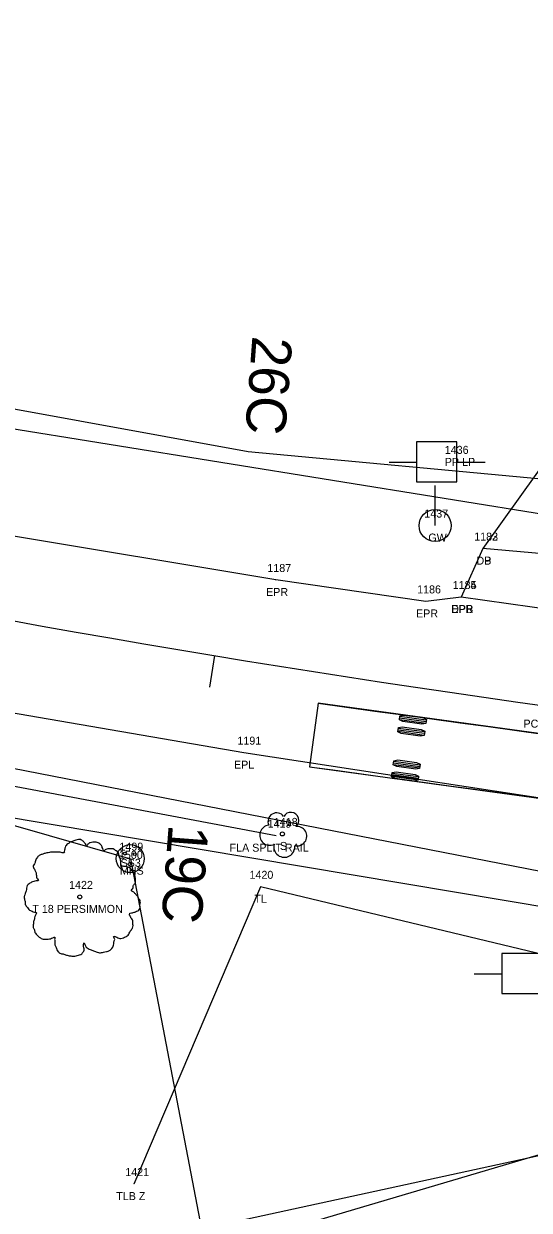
# Model space of a CAD drawing. Extents: x 1812113 to 1819860, y 1177290 to 1181185.
# Drawn here: x 1813468 to 1813531.1, y 1178709.1 to 1178857.4 of the extents above; entities that cross this region are included whole.
import ezdxf

# ---------------------------------------------------------------- set-up
doc = ezdxf.new("R2010")
doc.units = 0
for name, color, linetype in [('RD_EX_DR_Inlet', 7, 'Continuous'), ('RD_EX_Driveway', 7, 'Continuous'), ('RD_EX_Driveway_txCode', 7, 'Continuous'), ('RD_EX_Fence_Other', 7, 'Continuous'), ('RD_EX_Fence_Other_txCode', 7, 'Continuous'), ('RD_EX_H2O', 7, 'Continuous'), ('RD_EX_Road', 7, 'Continuous'), ('RD_EX_Road_txCode', 7, 'Continuous'), ('RD_EX_RW', 7, 'Continuous'), ('RD_EX_UT', 7, 'Continuous'), ('RD_EX_UT_txCode', 7, 'Continuous'), ('RD_EX_VEG', 7, 'Continuous'), ('RD_EX_VEG_txCode', 7, 'Continuous'), ('RD_HC_CL', 7, 'Continuous'), ('RD_HC_Data_Tic', 7, 'Continuous'), ('RD_HC_txCode', 7, 'Continuous'), ('RD_PD_CstnLmt', 7, 'Continuous'), ('RD_Sketch5', 7, 'Continuous'), ('RD_SMD_Locator', 7, 'Continuous')]:
    doc.layers.add(name, color=color, linetype=linetype)

msp = doc.modelspace()

# ---------------------------------------------------------------- linework, layer by layer
at = {"layer": 'RD_EX_DR_Inlet'}
for centre, radius in [((1813481.28, 1178753.05), 1.75), ((1813480.62, 1178753.68), 0.175), ((1813481.84, 1178753.61), 0.175), ((1813481.19, 1178752.38), 0.175)]:
    msp.add_circle(centre, radius, dxfattribs=at)
at = {"layer": 'RD_EX_Driveway'}
for points in [[(1813615.6, 1178795.77), (1813617.78, 1178806.55), (1813543.17, 1178816.74), (1813525.31, 1178791.79)], [(1813638.42, 1178791.25), (1813630.13, 1178786.38), (1813613.34, 1178784.52), (1813588.43, 1178786.24), (1813525.31, 1178791.79), (1813522.62, 1178785.74)]]:
    msp.add_lwpolyline(points, dxfattribs=at)
at = {"layer": 'RD_EX_Fence_Other'}
msp.add_lwpolyline([(1813499.51, 1178755.92), (1813424.16, 1178770.12), (1813422.76, 1178764.09)], dxfattribs=at)
at = {"layer": 'RD_EX_H2O'}
msp.add_lwpolyline([(1813499.62, 1178706.37), (1813533.11, 1178716.31), (1813566.87, 1178706.45), (1813581.02, 1178703.79), (1813602.73, 1178697.66), (1813630.18, 1178688.94), (1813658.74, 1178690.22), (1813683.52, 1178690.56), (1813733.77, 1178695.63), (1813767.86, 1178725.16), (1813778.94, 1178729.95)], dxfattribs=at)
at = {"layer": 'RD_EX_Road'}
for p, q in [((1813499.47, 1178787.87), (1813450.56, 1178796.06)), ((1813518.21, 1178785.19), (1813499.47, 1178787.87)), ((1813522.62, 1178785.74), (1813518.21, 1178785.19)), ((1813596.09, 1178775.31), (1813522.62, 1178785.74))]:
    msp.add_line(p, q, dxfattribs=at)
msp.add_lwpolyline([(1813732.94, 1178707.95), (1813689.88, 1178731.75), (1813641.71, 1178744.36), (1813593.37, 1178752.09), (1813544.49, 1178758.77), (1813495.45, 1178766.29), (1813446.8, 1178774.66), (1813426.54, 1178777.95), (1813403.21, 1178782.55), (1813398.65, 1178783.84), (1813350.68, 1178796.09), (1813343.23, 1178797.92), (1813318.7, 1178804.23), (1813303.26, 1178808.85), (1813256.8, 1178823.17), (1813209.81, 1178838.91), (1813163.27, 1178855.57)], dxfattribs=at)
at = {"layer": 'RD_EX_RW'}
for p, q in [((1813632.03, 1178780.07), (1813400.47, 1178817.38)), ((1813539.17, 1178745.92), (1813409.98, 1178767.65))]:
    msp.add_line(p, q, dxfattribs=at)
at = {"layer": 'RD_EX_UT'}
for p, q in [((1813522.06, 1178805.14), (1813517.06, 1178805.14)), ((1813517.06, 1178805.14), (1813517.06, 1178800.14)), ((1813522.06, 1178800.14), (1813522.06, 1178805.14)), ((1813513.63, 1178802.58), (1813517.1, 1178802.58)), ((1813521.99, 1178802.58), (1813525.63, 1178802.58)), ((1813517.06, 1178800.14), (1813522.06, 1178800.14)), ((1813519.36, 1178794.67), (1813519.36, 1178799.67)), ((1813532.69, 1178741.21), (1813527.69, 1178741.21)), ((1813527.69, 1178741.21), (1813527.69, 1178736.21)), ((1813524.26, 1178738.65), (1813527.73, 1178738.65)), ((1813527.69, 1178736.21), (1813532.69, 1178736.21))]:
    msp.add_line(p, q, dxfattribs=at)
for points in [[(1812996.89, 1178919.95), (1813204.49, 1178832.44), (1813481.3, 1178753.03), (1813490.2, 1178706.76)], [(1813817.45, 1178777.9), (1813490.2, 1178706.76), (1813294.33, 1178669.42)]]:
    msp.add_lwpolyline(points, dxfattribs=at)
msp.add_circle((1813519.36, 1178794.67), 2, dxfattribs=at)
at = {"layer": 'RD_EX_VEG'}
msp.add_lwpolyline([(1813615.69, 1178721.17), (1813497.56, 1178749.53), (1813481.72, 1178712.39)], dxfattribs=at)
for centre, radius in [((1813500.28, 1178756.14), 0.25), ((1813474.98, 1178748.27), 0.25), ((1813474.97, 1178748.25), 0.0001)]:
    msp.add_circle(centre, radius, dxfattribs=at)
for centre, radius, start, end in [((1813499.56, 1178757.69), 1.08, 34.9763, 204.756), ((1813501.33, 1178757.84), 0.995, 308.7626, 152.0467), ((1813498.72, 1178755.98), 1.26, 96.4518, 294.734), ((1813502.12, 1178755.86), 1.22, 256.5667, 98.1046), ((1813500.53, 1178754.54), 1.32, 166.8827, 5.7589)]:
    msp.add_arc(centre, radius, start, end, dxfattribs=at)
for points in [[(1813475.11, 1178755.44), (1813474.81, 1178755.46), (1813474.49, 1178755.36), (1813474.24, 1178755.26), (1813474.02, 1178755.19), (1813473.79, 1178755.09), (1813473.49, 1178754.91), (1813473.27, 1178754.71), (1813473.14, 1178754.46), (1813473.09, 1178754.24), (1813473.04, 1178753.96), (1813473.04, 1178753.79), (1813472.92, 1178753.76), (1813472.77, 1178753.79), (1813472.52, 1178753.86), (1813472.27, 1178753.86), (1813472.02, 1178753.86), (1813471.67, 1178753.84), (1813471.32, 1178753.84), (1813471.04, 1178753.79), (1813470.72, 1178753.74), (1813470.34, 1178753.61), (1813469.99, 1178753.49), (1813469.69, 1178753.24), (1813469.44, 1178752.76), (1813469.32, 1178752.41), (1813469.17, 1178752.16), (1813469.32, 1178751.72), (1813469.49, 1178751.37), (1813469.52, 1178751.17), (1813469.59, 1178750.74), (1813469.69, 1178750.52), (1813469.82, 1178750.32), (1813469.74, 1178750.29), (1813469.37, 1178750.24), (1813469.07, 1178750.14), (1813468.64, 1178749.92), (1813468.42, 1178749.69), (1813468.32, 1178749.37), (1813468.29, 1178749.02), (1813468.19, 1178748.82), (1813468.12, 1178748.54), (1813468.09, 1178748.47), (1813468.04, 1178748.14), (1813468.14, 1178747.69), (1813468.17, 1178747.34), (1813468.29, 1178747.12), (1813468.44, 1178746.94), (1813468.62, 1178746.69), (1813469.02, 1178746.47), (1813469.34, 1178746.37), (1813469.54, 1178746.34), (1813469.37, 1178745.84), (1813469.32, 1178745.49), (1813469.19, 1178745.09), (1813469.19, 1178745.02), (1813469.14, 1178744.54), (1813469.29, 1178744.22), (1813469.37, 1178743.84), (1813469.54, 1178743.62), (1813469.82, 1178743.32), (1813470.14, 1178743.09), (1813470.64, 1178742.97), (1813471.04, 1178742.99), (1813471.62, 1178743.17), (1813471.87, 1178743.24), (1813471.84, 1178743.07), (1813471.87, 1178742.69), (1813471.87, 1178742.27), (1813472.02, 1178741.94), (1813472.12, 1178741.67), (1813472.27, 1178741.42), (1813472.59, 1178741.19), (1813472.99, 1178741.12), (1813473.42, 1178740.97), (1813473.87, 1178740.89), (1813474.36, 1178740.87), (1813474.96, 1178741.02), (1813475.24, 1178741.14), (1813475.34, 1178741.32), (1813475.54, 1178741.69), (1813475.49, 1178741.92), (1813475.51, 1178742.52), (1813475.61, 1178742.34), (1813475.79, 1178741.99), (1813476.29, 1178741.69), (1813476.69, 1178741.52), (1813477.16, 1178741.37), (1813477.46, 1178741.29), (1813477.94, 1178741.37), (1813478.31, 1178741.44), (1813478.69, 1178741.57), (1813478.99, 1178741.84), (1813479.16, 1178742.12), (1813479.21, 1178742.39), (1813479.29, 1178742.77), (1813479.34, 1178742.94)], [(1813479.34, 1178742.94), (1813479.26, 1178743.12), (1813479.21, 1178743.37), (1813479.29, 1178743.34), (1813479.46, 1178743.29), (1813479.74, 1178743.17), (1813479.96, 1178743.09), (1813480.29, 1178743.12), (1813480.56, 1178743.22), (1813481.01, 1178743.49), (1813481.29, 1178743.97), (1813481.56, 1178744.37), (1813481.64, 1178744.69), (1813481.59, 1178744.92), (1813481.56, 1178745.42), (1813481.36, 1178745.67), (1813481.31, 1178745.79), (1813481.21, 1178746.19), (1813481.29, 1178746.24), (1813481.56, 1178746.29), (1813481.94, 1178746.42), (1813482.21, 1178746.54), (1813482.44, 1178746.72), (1813482.51, 1178746.94), (1813482.49, 1178747.34), (1813482.54, 1178747.74), (1813482.46, 1178747.89), (1813482.36, 1178748.04), (1813482.29, 1178748.24), (1813482.14, 1178748.39), (1813482.04, 1178748.54), (1813481.94, 1178748.64), (1813481.81, 1178748.79), (1813481.64, 1178748.92), (1813481.49, 1178748.97), (1813481.44, 1178749.12), (1813481.59, 1178749.32), (1813481.64, 1178749.42), (1813481.66, 1178749.64), (1813481.89, 1178749.99), (1813481.94, 1178750.39), (1813481.89, 1178750.82), (1813481.84, 1178751.09), (1813481.69, 1178751.37), (1813481.49, 1178751.62), (1813481.36, 1178751.79), (1813481.19, 1178751.92), (1813480.86, 1178752.04), (1813480.61, 1178752.09), (1813480.26, 1178752.09), (1813480.06, 1178752.14), (1813480.09, 1178752.19), (1813480.09, 1178752.34), (1813480.09, 1178752.61), (1813480.01, 1178753.06), (1813479.86, 1178753.56), (1813479.86, 1178753.59), (1813479.76, 1178753.84), (1813479.54, 1178754.04), (1813479.36, 1178754.14), (1813479.16, 1178754.26), (1813478.91, 1178754.29), (1813478.61, 1178754.29), (1813478.34, 1178754.24), (1813478.14, 1178754.14), (1813477.96, 1178754.01), (1813477.89, 1178754.16), (1813477.79, 1178754.46), (1813477.74, 1178754.61), (1813477.59, 1178754.79), (1813477.36, 1178754.99), (1813476.91, 1178755.11), (1813476.29, 1178755.04), (1813475.99, 1178754.84), (1813475.84, 1178754.66), (1813475.79, 1178754.79), (1813475.59, 1178754.99), (1813475.49, 1178755.16), (1813475.31, 1178755.29), (1813475.16, 1178755.39), (1813475.06, 1178755.44)]]:
    msp.add_spline(points, degree=3, dxfattribs=at)
at = {"layer": 'RD_HC_CL'}
msp.add_arc((1813766.93, 1180445.18), 1689.31, 243.58271, 262.2191, dxfattribs=at)
at = {"layer": 'RD_HC_Data_Tic'}
msp.add_line((1813491.82, 1178778.42), (1813491.17, 1178774.47), dxfattribs=at)
at = {"layer": 'RD_PD_CstnLmt'}
for p, q in [((1813496.03, 1178803.9), (1813447.58, 1178812.68)), ((1813545.13, 1178799.29), (1813496.03, 1178803.9)), ((1813538.44, 1178750.29), (1813429.25, 1178771.59))]:
    msp.add_line(p, q, dxfattribs=at)
at = {"layer": 'RD_Sketch5'}
for p, q in [((1813504.75, 1178772.46), (1813503.67, 1178764.53)), ((1813540.22, 1178767.61), (1813504.75, 1178772.46)), ((1813514.93, 1178770.65), (1813518.24, 1178770.2)), ((1813514.96, 1178770.85), (1813518.26, 1178770.4)), ((1813514.73, 1178769.16), (1813518.03, 1178768.71)), ((1813514.76, 1178769.37), (1813518.06, 1178768.92)), ((1813514.91, 1178770.44), (1813518.21, 1178769.99)), ((1813514.7, 1178768.96), (1813518, 1178768.5)), ((1813514.14, 1178764.83), (1813517.44, 1178764.38)), ((1813514.17, 1178765.03), (1813517.47, 1178764.58)), ((1813514.19, 1178765.24), (1813517.5, 1178764.79)), ((1813503.67, 1178764.53), (1813539.14, 1178759.69)), ((1813513.94, 1178763.34), (1813517.24, 1178762.89)), ((1813513.96, 1178763.55), (1813517.27, 1178763.1)), ((1813513.99, 1178763.75), (1813517.29, 1178763.3))]:
    msp.add_line(p, q, dxfattribs=at)
for points in [[(1813504.75, 1178772.46), (1813508.3, 1178771.98), (1813511.85, 1178771.49), (1813515.39, 1178771.01), (1813518.94, 1178770.52), (1813522.49, 1178770.04), (1813526.03, 1178769.55), (1813529.58, 1178769.07), (1813533.13, 1178768.58)], [(1813503.67, 1178764.53), (1813507.22, 1178764.05), (1813510.76, 1178763.56), (1813514.31, 1178763.08), (1813517.86, 1178762.6), (1813521.4, 1178762.11), (1813524.95, 1178761.63), (1813528.5, 1178761.14), (1813532.04, 1178760.66)]]:
    msp.add_lwpolyline(points, dxfattribs=at)
for points in [[(1813514.9, 1178770.39), (1813514.97, 1178770.91), (1813515.45, 1178771), (1813517.83, 1178770.67), (1813518.27, 1178770.45), (1813518.2, 1178769.94), (1813517.72, 1178769.85), (1813515.34, 1178770.17)], [(1813514.7, 1178768.9), (1813514.77, 1178769.42), (1813515.25, 1178769.51), (1813517.63, 1178769.19), (1813518.07, 1178768.97), (1813518, 1178768.45), (1813517.51, 1178768.36), (1813515.14, 1178768.69)], [(1813514.13, 1178764.78), (1813514.2, 1178765.29), (1813514.69, 1178765.38), (1813517.06, 1178765.06), (1813517.5, 1178764.84), (1813517.43, 1178764.33), (1813516.95, 1178764.23), (1813514.57, 1178764.56)], [(1813513.93, 1178763.29), (1813514, 1178763.81), (1813514.48, 1178763.9), (1813516.86, 1178763.57), (1813517.3, 1178763.35), (1813517.23, 1178762.84), (1813516.75, 1178762.75), (1813514.37, 1178763.07)]]:
    msp.add_lwpolyline(points, close=True, dxfattribs=at)
at = {"layer": 'RD_SMD_Locator'}
for centre in [(1813525.31, 1178791.79), (1813525.31, 1178791.79), (1813499.47, 1178787.87), (1813522.62, 1178785.74), (1813522.62, 1178785.74), (1813518.21, 1178785.19), (1813495.45, 1178766.29), (1813499.51, 1178755.92), (1813481.3, 1178753.03), (1813497.56, 1178749.53), (1813481.72, 1178712.39)]:
    msp.add_circle(centre, 0.001, dxfattribs=at)

# ---------------------------------------------------------------- texts
at = {"layer": 'RD_EX_Driveway_txCode'}
for s, p in [('1182', (1813524.25, 1178792.79)), ('1183', (1813524.25, 1178792.79)), ('DP', (1813524.53, 1178789.79)), ('DB', (1813524.53, 1178789.79)), ('1184', (1813521.56, 1178786.74)), ('DPB', (1813521.37, 1178783.74))]:
    msp.add_text(s, height=1, dxfattribs=at).set_placement(p)
at = {"layer": 'RD_EX_Fence_Other_txCode'}
for s, p in [('1419', (1813498.45, 1178756.92)), ('FLA SPLIT RAIL', (1813493.69, 1178753.92))]:
    msp.add_text(s, height=1, dxfattribs=at).set_placement(p)
at = {"layer": 'RD_EX_Road_txCode'}
for s, p in [('1187', (1813498.41, 1178788.87)), ('1186', (1813517.12, 1178786.19)), ('1185', (1813521.56, 1178786.74)), ('EPR', (1813498.25, 1178785.87)), ('EPR', (1813516.98, 1178783.19)), ('EPR', (1813521.39, 1178783.74)), ('1191', (1813494.67, 1178767.29)), ('EPL', (1813494.24, 1178764.29))]:
    msp.add_text(s, height=1, dxfattribs=at).set_placement(p)
at = {"layer": 'RD_EX_UT_txCode'}
for s, p in [('1436', (1813520.57, 1178803.63)), ('PP LP', (1813520.57, 1178802.13)), ('1437', (1813518.02, 1178795.67)), ('GW', (1813518.52, 1178792.67)), ('1499', (1813479.93, 1178754.05)), ('1500', (1813479.87, 1178753.03)), ('SS3', (1813480.07, 1178752.03)), ('MHS', (1813479.99, 1178751.05))]:
    msp.add_text(s, height=1, dxfattribs=at).set_placement(p)
at = {"layer": 'RD_EX_VEG_txCode'}
for s, p in [('1418', (1813499.22, 1178757.14)), ('S', (1813499.98, 1178754.14)), ('1420', (1813496.18, 1178750.53)), ('1422', (1813473.64, 1178749.27)), ('TL', (1813496.79, 1178747.53)), ('T 18 PERSIMMON', (1813469.05, 1178746.27)), ('1421', (1813480.66, 1178713.39)), ('TLB Z', (1813479.53, 1178710.39))]:
    msp.add_text(s, height=1, dxfattribs=at).set_placement(p)
at = {"layer": 'RD_HC_txCode'}
msp.add_text('PC 16+53.07 RD S-41', height=1, dxfattribs=at).set_placement((1813530.4, 1178769.42))
at = {"layer": 'RD_PD_CstnLmt'}
for s, p in [('26C', (1813496.55, 1178818.44)), ('19C', (1813486.09, 1178757.4))]:
    msp.add_text(s, height=5, rotation=265.7319, dxfattribs=at).set_placement(p)

doc.saveas('drawing.dxf')
